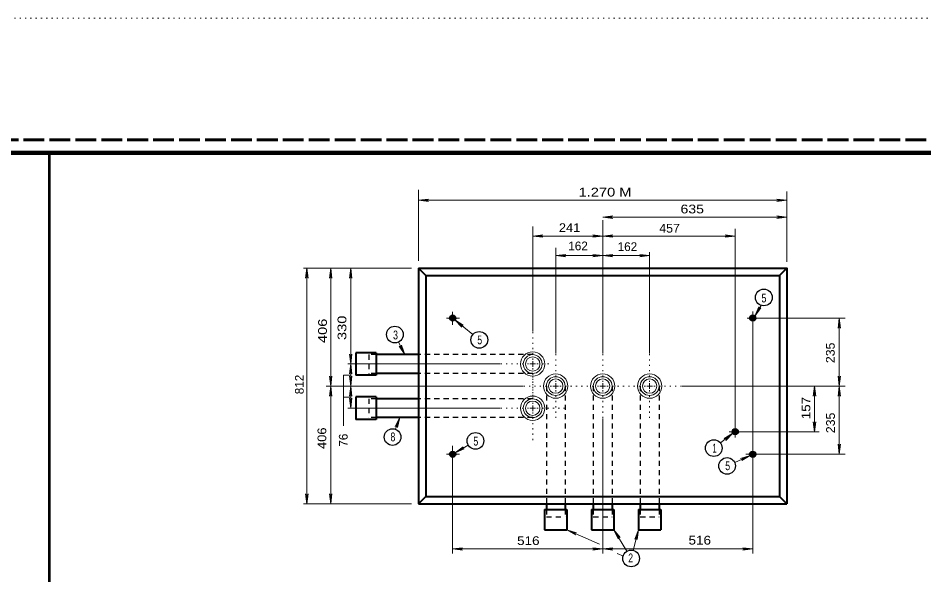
# Model space of a CAD drawing. Extents: x 312583 to 312854, y 144419 to 144597.
# Drawn here: x 312705.5 to 312784.1, y 144548.5 to 144596.8 of the extents above; entities that cross this region are included whole.
import ezdxf

# ---------------------------------------------------------------- set-up
doc = ezdxf.new("R2010")
doc.units = 0
doc.header["$LTSCALE"] = 0.3
for name, pattern in [('DOTTED', [1.5, 0.3, -1.2]), ('LONG_DASHED', [7.5, 6, -1.5]), ('SHORT_DASHED', [2.7, 1.5, -1.2])]:
    doc.linetypes.add(name, pattern=pattern)
for name, color, linetype, lineweight in [('1', 7, 'Continuous', 25), ('2', 7, 'Continuous', 13), ('52', 7, 'Continuous', 25), ('62', 7, 'DOTTED', 13), ('63', 7, 'LONG_DASHED', 60)]:
    doc.layers.add(name, color=color, linetype=linetype, lineweight=lineweight)

msp = doc.modelspace()

# ---------------------------------------------------------------- linework, layer by layer
at = {"layer": '1', "lineweight": 40}
for p, q in [((312740.216, 144575.0795), (312740.216, 144554.6325)), ((312740.86, 144574.4431), (312740.216, 144575.0795)), ((312771.5267, 144574.4431), (312772.163, 144575.0795)), ((312740.86, 144574.4431), (312740.86, 144555.2765)), ((312736.5437, 144567.7501), (312734.788, 144567.7501)), ((312734.788, 144567.7501), (312734.788, 144565.7951)), ((312736.5437, 144567.7501), (312736.5437, 144565.7951)), ((312740.216, 144567.5891), (312736.5437, 144567.5891)), ((312740.216, 144565.9561), (312736.5437, 144565.9561)), ((312736.5437, 144565.7951), (312734.788, 144565.7951)), ((312736.5437, 144563.9168), (312734.788, 144563.9168)), ((312734.788, 144563.9168), (312734.788, 144561.9618)), ((312736.5437, 144563.9168), (312736.5437, 144561.9618)), ((312740.216, 144563.7558), (312736.5437, 144563.7558)), ((312736.5437, 144561.9618), (312734.788, 144561.9618)), ((312740.216, 144562.1228), (312736.5437, 144562.1228)), ((312740.86, 144555.2765), (312740.216, 144554.6325)), ((312740.86, 144555.2765), (312771.5267, 144555.2765)), ((312771.5267, 144555.2765), (312772.163, 144554.6325)), ((312740.216, 144554.6325), (312772.163, 144554.6325)), ((312751.141, 144554.1571), (312751.141, 144552.4015)), ((312751.141, 144554.1571), (312753.0884, 144554.1571)), ((312751.302, 144554.6325), (312751.302, 144554.1571)), ((312752.935, 144554.6325), (312752.935, 144554.1571)), ((312753.0884, 144554.1571), (312753.0884, 144552.4015)), ((312755.212, 144554.1571), (312755.212, 144552.4015)), ((312755.212, 144554.1571), (312757.167, 144554.1571)), ((312755.373, 144554.6325), (312755.373, 144554.1571)), ((312757.006, 144554.6325), (312757.006, 144554.1571)), ((312757.167, 144554.1571), (312757.167, 144552.4015)), ((312759.2907, 144554.1571), (312759.2907, 144552.4015)), ((312759.2907, 144554.1571), (312761.238, 144554.1571)), ((312759.4517, 144554.6325), (312759.4517, 144554.1571)), ((312761.077, 144554.6325), (312761.077, 144554.1571)), ((312761.238, 144554.1571), (312761.238, 144552.4015)), ((312751.141, 144552.4015), (312753.0884, 144552.4015)), ((312755.212, 144552.4015), (312757.167, 144552.4015)), ((312759.2907, 144552.4015), (312761.238, 144552.4015))]:
    msp.add_line(p, q, dxfattribs=at)
at = {"layer": '1', "linetype": 'SHORT_DASHED'}
for p, q in [((312735.9074, 144567.5891), (312735.9074, 144565.9561)), ((312736.5437, 144567.5891), (312735.9074, 144567.5891)), ((312750.1214, 144567.5891), (312740.216, 144567.5891)), ((312736.5437, 144565.9561), (312735.9074, 144565.9561)), ((312750.1214, 144565.9561), (312740.216, 144565.9561)), ((312751.302, 144564.8598), (312751.302, 144554.6325)), ((312752.935, 144564.8598), (312752.935, 144554.6325)), ((312755.373, 144564.8598), (312755.373, 144554.6325)), ((312757.006, 144564.8598), (312757.006, 144554.6325)), ((312759.4517, 144564.8598), (312759.4517, 144554.6325)), ((312761.077, 144564.8598), (312761.077, 144554.6325)), ((312735.9074, 144563.7558), (312735.9074, 144562.1228)), ((312736.5437, 144563.7558), (312735.9074, 144563.7558)), ((312750.1214, 144563.7558), (312740.216, 144563.7558)), ((312736.5437, 144562.1228), (312735.9074, 144562.1228)), ((312750.1214, 144562.1228), (312740.216, 144562.1228)), ((312751.302, 144554.1571), (312751.302, 144553.5131)), ((312752.935, 144554.1571), (312752.935, 144553.5131)), ((312755.373, 144554.1571), (312755.373, 144553.5131)), ((312757.006, 144554.1571), (312757.006, 144553.5131)), ((312759.4517, 144554.1571), (312759.4517, 144553.5131)), ((312761.077, 144554.1571), (312761.077, 144553.5131)), ((312751.302, 144553.5131), (312752.935, 144553.5131)), ((312755.373, 144553.5131), (312757.006, 144553.5131)), ((312759.4517, 144553.5131), (312761.077, 144553.5131))]:
    msp.add_line(p, q, dxfattribs=at)
at = {"layer": '1', "lineweight": 158}
msp.add_lwpolyline([(312616.5, 144423.1446), (312616.5, 144585.0846), (312849, 144585.0846)], dxfattribs=at)
at = {"layer": '1', "lineweight": 40}
for points in [[(312740.216, 144575.0795), (312772.163, 144575.0795), (312772.163, 144554.6325)], [(312740.86, 144574.4431), (312771.5267, 144574.4431), (312771.5267, 144555.2765)]]:
    msp.add_lwpolyline(points, dxfattribs=at)
for centre, radius in [((312743.1722, 144570.7663), 0.2396), ((312743.1722, 144570.7663), 0.2156), ((312743.1722, 144570.7663), 0.1941), ((312743.1722, 144570.7663), 0.1747), ((312743.1722, 144570.7663), 0.1572), ((312743.1722, 144570.7663), 0.1415), ((312743.1722, 144570.7663), 0.1273), ((312743.1722, 144570.7663), 0.1146), ((312743.1722, 144570.7663), 0.1031), ((312743.1722, 144570.7663), 0.0928), ((312743.1722, 144570.7663), 0.0835), ((312743.1722, 144570.7663), 0.0752), ((312743.1722, 144570.7663), 0.0677), ((312743.1722, 144570.7663), 0.0609), ((312743.1722, 144570.7663), 0.0548), ((312769.2069, 144570.7663), 0.2396), ((312769.2069, 144570.7663), 0.2156), ((312769.2069, 144570.7663), 0.1941), ((312769.2069, 144570.7663), 0.1747), ((312769.2069, 144570.7663), 0.1572), ((312769.2069, 144570.7663), 0.1415), ((312769.2069, 144570.7663), 0.1273), ((312769.2069, 144570.7663), 0.1146), ((312769.2069, 144570.7663), 0.1031), ((312769.2069, 144570.7663), 0.0928), ((312769.2069, 144570.7663), 0.0835), ((312769.2069, 144570.7663), 0.0752), ((312769.2069, 144570.7663), 0.0677), ((312769.2069, 144570.7663), 0.0609), ((312769.2069, 144570.7663), 0.0548), ((312767.6895, 144560.9038), 0.2396), ((312767.6895, 144560.9038), 0.2156), ((312767.6895, 144560.9038), 0.1941), ((312767.6895, 144560.9038), 0.1747), ((312767.6895, 144560.9038), 0.1572), ((312767.6895, 144560.9038), 0.1415), ((312767.6895, 144560.9038), 0.1273), ((312767.6895, 144560.9038), 0.1146), ((312767.6895, 144560.9038), 0.1031), ((312767.6895, 144560.9038), 0.0928), ((312767.6895, 144560.9038), 0.0835), ((312767.6895, 144560.9038), 0.0752), ((312767.6895, 144560.9038), 0.0677), ((312767.6895, 144560.9038), 0.0609), ((312767.6895, 144560.9038), 0.0548), ((312743.1722, 144558.9469), 0.2396), ((312743.1722, 144558.9469), 0.2156), ((312743.1722, 144558.9469), 0.1941), ((312743.1722, 144558.9469), 0.1747), ((312743.1722, 144558.9469), 0.1572), ((312743.1722, 144558.9469), 0.1415), ((312743.1722, 144558.9469), 0.1273), ((312743.1722, 144558.9469), 0.1146), ((312743.1722, 144558.9469), 0.1031), ((312743.1722, 144558.9469), 0.0928), ((312743.1722, 144558.9469), 0.0835), ((312743.1722, 144558.9469), 0.0752), ((312743.1722, 144558.9469), 0.0677), ((312743.1722, 144558.9469), 0.0609), ((312743.1722, 144558.9469), 0.0548), ((312769.2069, 144558.9469), 0.2396), ((312769.2069, 144558.9469), 0.2156), ((312769.2069, 144558.9469), 0.1941), ((312769.2069, 144558.9469), 0.1747), ((312769.2069, 144558.9469), 0.1572), ((312769.2069, 144558.9469), 0.1415), ((312769.2069, 144558.9469), 0.1273), ((312769.2069, 144558.9469), 0.1146), ((312769.2069, 144558.9469), 0.1031), ((312769.2069, 144558.9469), 0.0928), ((312769.2069, 144558.9469), 0.0835), ((312769.2069, 144558.9469), 0.0752), ((312769.2069, 144558.9469), 0.0677), ((312769.2069, 144558.9469), 0.0609), ((312769.2069, 144558.9469), 0.0548)]:
    msp.add_circle(centre, radius, dxfattribs=at)
at = {"layer": '1', "lineweight": 13}
for centre, radius in [((312750.1201, 144566.7733), 1.0542), ((312750.1201, 144566.7733), 0.8146), ((312750.1201, 144566.7733), 0.6232), ((312752.1166, 144564.8566), 1.0542), ((312756.1895, 144564.8566), 1.0542), ((312760.2625, 144564.8566), 1.0542), ((312752.1166, 144564.8566), 0.8146), ((312752.1166, 144564.8566), 0.6232), ((312756.1895, 144564.8566), 0.8146), ((312756.1895, 144564.8566), 0.6232), ((312760.2625, 144564.8566), 0.8146), ((312760.2625, 144564.8566), 0.6232), ((312750.1201, 144562.9399), 1.0542), ((312750.1201, 144562.9399), 0.8146), ((312750.1201, 144562.9399), 0.6232)]:
    msp.add_circle(centre, radius, dxfattribs=at)
at = {"layer": '2', "lineweight": 53}
msp.add_line((312708.1809, 144585.0846), (312708.1809, 144423.0846), dxfattribs=at)
at = {"layer": '2'}
for p, q in [((312740.216, 144575.7388), (312740.216, 144581.8982)), ((312772.163, 144575.6315), (312772.163, 144581.7487)), ((312740.216, 144580.9791), (312741.0824, 144581.0864)), ((312740.216, 144580.9791), (312772.163, 144580.9791)), ((312740.216, 144580.9791), (312741.0824, 144580.8717)), ((312741.0824, 144581.0864), (312740.8064, 144580.9791)), ((312741.0824, 144580.8717), (312740.8064, 144580.9791)), ((312771.2967, 144581.0864), (312771.5727, 144580.9791)), ((312772.163, 144580.9791), (312771.2967, 144581.0864)), ((312771.2967, 144580.8717), (312771.5727, 144580.9791)), ((312772.163, 144580.9791), (312771.2967, 144580.8717)), ((312756.1934, 144579.5109), (312757.0597, 144579.6182)), ((312756.1934, 144579.5109), (312772.163, 144579.5109)), ((312756.1934, 144579.5109), (312757.0597, 144579.4036)), ((312756.1934, 144567.6811), (312756.1934, 144579.2578)), ((312757.0597, 144579.6182), (312756.7837, 144579.5109)), ((312757.0597, 144579.4036), (312756.7837, 144579.5109)), ((312771.2967, 144579.6182), (312771.5727, 144579.5109)), ((312772.163, 144579.5109), (312771.2967, 144579.6182)), ((312771.2967, 144579.4036), (312771.5727, 144579.5109)), ((312772.163, 144579.5109), (312771.2967, 144579.4036)), ((312750.1214, 144569.5978), (312750.1214, 144578.7058)), ((312767.6934, 144578.4911), (312767.6934, 144560.4055)), ((312750.1214, 144577.8787), (312750.9877, 144577.9861)), ((312750.1214, 144577.8787), (312756.1934, 144577.8787)), ((312750.1214, 144577.8787), (312750.9877, 144577.7714)), ((312750.9877, 144577.9861), (312750.7117, 144577.8787)), ((312750.9877, 144577.7714), (312750.7117, 144577.8787)), ((312755.327, 144577.9861), (312755.603, 144577.8787)), ((312756.1934, 144577.8787), (312755.327, 144577.9861)), ((312755.327, 144577.7714), (312755.603, 144577.8787)), ((312756.1934, 144577.8787), (312755.327, 144577.7714)), ((312756.1934, 144577.8787), (312757.0597, 144577.9861)), ((312756.1934, 144577.8787), (312767.6934, 144577.8787)), ((312756.1934, 144577.8787), (312757.0597, 144577.7714)), ((312757.0597, 144577.9861), (312756.7837, 144577.8787)), ((312757.0597, 144577.7714), (312756.7837, 144577.8787)), ((312766.827, 144577.9861), (312767.103, 144577.8787)), ((312767.6934, 144577.8787), (312766.827, 144577.9861)), ((312766.827, 144577.7714), (312767.103, 144577.8787)), ((312767.6934, 144577.8787), (312766.827, 144577.7714)), ((312752.1147, 144567.6811), (312752.1147, 144576.8658)), ((312752.1147, 144576.1758), (312752.981, 144576.2831)), ((312752.1147, 144576.1758), (312752.981, 144576.0685)), ((312752.1147, 144576.1758), (312756.1934, 144576.1758)), ((312752.981, 144576.2831), (312752.705, 144576.1758)), ((312752.981, 144576.0685), (312752.705, 144576.1758)), ((312755.327, 144576.2831), (312755.603, 144576.1758)), ((312756.1934, 144576.1758), (312755.327, 144576.2831)), ((312755.327, 144576.0685), (312755.603, 144576.1758)), ((312756.1934, 144576.1758), (312755.327, 144576.0685)), ((312756.1934, 144576.1758), (312757.0597, 144576.2831)), ((312756.1934, 144576.1758), (312760.2644, 144576.1758)), ((312756.1934, 144576.1758), (312757.0597, 144576.0685)), ((312757.0597, 144576.2831), (312756.7837, 144576.1758)), ((312757.0597, 144576.0685), (312756.7837, 144576.1758)), ((312759.398, 144576.2831), (312759.674, 144576.1758)), ((312760.2644, 144576.1758), (312759.398, 144576.2831)), ((312759.398, 144576.0685), (312759.674, 144576.1758)), ((312760.2644, 144576.1758), (312759.398, 144576.0685)), ((312760.2644, 144567.6811), (312760.2644, 144576.4825)), ((312739.618, 144575.0795), (312730.234, 144575.0795)), ((312730.5254, 144575.0795), (312730.418, 144574.2131)), ((312730.5254, 144554.6325), (312730.5254, 144575.0795)), ((312730.5254, 144575.0795), (312730.6327, 144574.2131)), ((312732.5954, 144575.0795), (312732.488, 144574.2131)), ((312732.5954, 144575.0795), (312732.7027, 144574.2131)), ((312734.3357, 144575.0795), (312734.2284, 144574.2131)), ((312734.3357, 144575.0795), (312734.443, 144574.2131)), ((312730.418, 144574.2131), (312730.5254, 144574.4891)), ((312730.6327, 144574.2131), (312730.5254, 144574.4891)), ((312732.488, 144574.2131), (312732.5954, 144574.4891)), ((312732.7027, 144574.2131), (312732.5954, 144574.4891)), ((312734.2284, 144574.2131), (312734.3357, 144574.4891)), ((312734.443, 144574.2131), (312734.3357, 144574.4891)), ((312769.9244, 144571.8595), (312769.3877, 144570.9395)), ((312769.3877, 144570.9395), (312769.7327, 144571.7445)), ((312769.3877, 144570.9395), (312769.9167, 144571.6371)), ((312769.7327, 144571.7445), (312769.6867, 144571.4531)), ((312769.9167, 144571.6371), (312769.6867, 144571.4531)), ((312742.6387, 144570.7631), (312743.758, 144570.7631)), ((312743.1754, 144571.2998), (312743.1754, 144570.1805)), ((312744.9234, 144569.3295), (312743.3594, 144570.6175)), ((312743.3594, 144570.6175), (312743.9574, 144569.9811)), ((312743.3594, 144570.6175), (312744.0954, 144570.1498)), ((312768.736, 144570.7631), (312777.2154, 144570.7631)), ((312769.2037, 144571.3228), (312769.2037, 144550.3315)), ((312776.717, 144570.7631), (312776.6097, 144569.8968)), ((312776.717, 144570.7631), (312776.8244, 144569.8968)), ((312743.9574, 144569.9811), (312743.8117, 144570.2418)), ((312744.0954, 144570.1498), (312743.8117, 144570.2418)), ((312776.6097, 144569.8968), (312776.717, 144570.1728)), ((312776.8244, 144569.8968), (312776.717, 144570.1728)), ((312738.491, 144568.6778), (312739.0277, 144567.5891)), ((312738.5447, 144568.3175), (312738.767, 144568.1181)), ((312739.0277, 144567.5891), (312738.5447, 144568.3175)), ((312738.7364, 144568.4095), (312738.767, 144568.1181)), ((312739.0277, 144567.5891), (312738.7364, 144568.4095)), ((312734.2284, 144567.6428), (312734.3357, 144567.3668)), ((312734.3357, 144566.7765), (312734.2284, 144567.6428)), ((312734.443, 144567.6428), (312734.3357, 144567.3668)), ((312734.3357, 144566.7765), (312734.443, 144567.6428)), ((312747.3, 144566.7765), (312734.0904, 144566.7765)), ((312734.3357, 144566.7765), (312734.2284, 144565.9101)), ((312734.3357, 144566.7765), (312734.443, 144565.9101)), ((312750.1214, 144566.7765), (312749.876, 144566.7765)), ((312750.1214, 144566.7765), (312750.1214, 144567.0218)), ((312750.1214, 144566.7765), (312750.3667, 144566.7765)), ((312750.1214, 144566.7765), (312750.1214, 144566.5311)), ((312734.2284, 144565.9101), (312734.3357, 144566.1861)), ((312734.443, 144565.9101), (312734.3357, 144566.1861)), ((312732.488, 144565.7261), (312732.5954, 144565.4501)), ((312732.5954, 144564.8598), (312732.488, 144565.7261)), ((312732.7027, 144565.7261), (312732.5954, 144565.4501)), ((312732.5954, 144564.8598), (312732.7027, 144565.7261)), ((312734.2284, 144565.7261), (312734.3357, 144565.4501)), ((312734.3357, 144564.8598), (312734.2284, 144565.7261)), ((312734.443, 144565.7261), (312734.3357, 144565.4501)), ((312734.3357, 144564.8598), (312734.443, 144565.7261)), ((312752.1147, 144564.8598), (312752.1147, 144565.1051)), ((312756.1934, 144564.8598), (312756.1934, 144565.1051)), ((312760.2644, 144564.8598), (312760.2644, 144565.1051)), ((312776.6097, 144565.7261), (312776.717, 144565.4501)), ((312776.717, 144564.8598), (312776.6097, 144565.7261)), ((312776.8244, 144565.7261), (312776.717, 144565.4501)), ((312776.717, 144564.8598), (312776.8244, 144565.7261)), ((312749.2934, 144564.8598), (312732.2044, 144564.8598)), ((312732.5954, 144564.8598), (312732.488, 144563.9935)), ((312732.5954, 144564.8598), (312732.7027, 144563.9935)), ((312734.3357, 144564.8598), (312734.2284, 144563.9935)), ((312734.3357, 144564.8598), (312734.443, 144563.9935)), ((312752.1147, 144564.8598), (312751.8694, 144564.8598)), ((312752.1147, 144564.8598), (312752.36, 144564.8598)), ((312752.1147, 144564.8598), (312752.1147, 144564.6145)), ((312756.1934, 144564.8598), (312755.948, 144564.8598)), ((312756.1934, 144564.8598), (312756.4387, 144564.8598)), ((312756.1934, 144564.8598), (312756.1934, 144564.6145)), ((312760.2644, 144564.8598), (312760.019, 144564.8598)), ((312760.2644, 144564.8598), (312760.5097, 144564.8598)), ((312760.2644, 144564.8598), (312760.2644, 144564.6145)), ((312763.0857, 144564.8598), (312777.2154, 144564.8598)), ((312774.5627, 144564.8598), (312774.4554, 144563.9935)), ((312774.5627, 144560.9038), (312774.5627, 144564.8598)), ((312774.5627, 144564.8598), (312774.67, 144563.9935)), ((312776.717, 144564.8598), (312776.6097, 144563.9935)), ((312776.717, 144564.8598), (312776.8244, 144563.9935)), ((312732.488, 144563.9935), (312732.5954, 144564.2695)), ((312732.7027, 144563.9935), (312732.5954, 144564.2695)), ((312734.2284, 144563.9935), (312734.3357, 144564.2695)), ((312734.2284, 144563.8095), (312734.3357, 144563.5335)), ((312734.3357, 144562.9431), (312734.2284, 144563.8095)), ((312734.443, 144563.9935), (312734.3357, 144564.2695)), ((312734.443, 144563.8095), (312734.3357, 144563.5335)), ((312734.3357, 144562.9431), (312734.443, 144563.8095)), ((312774.4554, 144563.9935), (312774.5627, 144564.2695)), ((312774.67, 144563.9935), (312774.5627, 144564.2695)), ((312776.6097, 144563.9935), (312776.717, 144564.2695)), ((312776.8244, 144563.9935), (312776.717, 144564.2695)), ((312747.3, 144562.9431), (312734.0904, 144562.9431)), ((312750.1214, 144562.9431), (312749.876, 144562.9431)), ((312750.1214, 144562.9431), (312750.1214, 144563.1885)), ((312750.1214, 144562.9431), (312750.3667, 144562.9431)), ((312750.1214, 144562.9431), (312750.1214, 144562.6978)), ((312738.606, 144562.1228), (312738.1997, 144561.3561)), ((312738.2227, 144561.1185), (312738.606, 144562.1228)), ((312738.606, 144562.1228), (312738.399, 144561.2795)), ((312756.1934, 144562.0385), (312756.1934, 144550.3315)), ((312738.1997, 144561.3561), (312738.399, 144561.5708)), ((312738.399, 144561.2795), (312738.399, 144561.5708)), ((312774.4554, 144561.7701), (312774.5627, 144561.4941)), ((312774.5627, 144560.9038), (312774.4554, 144561.7701)), ((312774.67, 144561.7701), (312774.5627, 144561.4941)), ((312774.5627, 144560.9038), (312774.67, 144561.7701)), ((312766.3977, 144559.9301), (312767.4864, 144560.7735)), ((312767.4864, 144560.7735), (312766.735, 144560.3211)), ((312766.735, 144560.3211), (312767.0187, 144560.4055)), ((312767.4864, 144560.7735), (312766.8654, 144560.1525)), ((312766.8654, 144560.1525), (312767.0187, 144560.4055)), ((312767.172, 144560.9038), (312774.9614, 144560.9038)), ((312743.1754, 144559.6695), (312743.1754, 144550.3315)), ((312744.5247, 144559.7385), (312743.3824, 144559.0638)), ((312743.3824, 144559.0638), (312744.0724, 144559.6005)), ((312744.0724, 144559.6005), (312743.8884, 144559.3628)), ((312776.6097, 144559.8151), (312776.717, 144559.5391)), ((312776.717, 144558.9488), (312776.6097, 144559.8151)), ((312776.8244, 144559.8151), (312776.717, 144559.5391)), ((312776.717, 144558.9488), (312776.8244, 144559.8151)), ((312742.6387, 144558.9488), (312743.758, 144558.9488)), ((312743.3824, 144559.0638), (312744.1797, 144559.4088)), ((312744.1797, 144559.4088), (312743.8884, 144559.3628)), ((312767.6397, 144558.2281), (312768.989, 144558.8491)), ((312768.989, 144558.8491), (312768.1534, 144558.5885)), ((312768.989, 144558.8491), (312768.2454, 144558.3891)), ((312768.6057, 144558.9488), (312777.2154, 144558.9488)), ((312768.1534, 144558.5885), (312768.4524, 144558.6038)), ((312768.2454, 144558.3891), (312768.4524, 144558.6038)), ((312730.418, 144555.4988), (312730.5254, 144555.2228)), ((312730.5254, 144554.6325), (312730.418, 144555.4988)), ((312730.6327, 144555.4988), (312730.5254, 144555.2228)), ((312730.5254, 144554.6325), (312730.6327, 144555.4988)), ((312732.488, 144555.4988), (312732.5954, 144555.2228)), ((312732.5954, 144554.6325), (312732.488, 144555.4988)), ((312732.7027, 144555.4988), (312732.5954, 144555.2228)), ((312732.5954, 144554.6325), (312732.7027, 144555.4988)), ((312739.618, 144554.6325), (312730.234, 144554.6325)), ((312753.0884, 144552.4015), (312753.8397, 144551.9491)), ((312753.0884, 144552.4015), (312753.924, 144552.1408)), ((312755.9174, 144551.1365), (312753.0884, 144552.4015)), ((312753.8397, 144551.9491), (312753.6327, 144552.1561)), ((312753.924, 144552.1408), (312753.6327, 144552.1561)), ((312758.2864, 144550.5308), (312757.167, 144552.4015)), ((312757.167, 144552.4015), (312757.5197, 144551.5965)), ((312757.167, 144552.4015), (312757.7037, 144551.7115)), ((312757.5197, 144551.5965), (312757.466, 144551.8878)), ((312757.7037, 144551.7115), (312757.466, 144551.8878)), ((312758.8384, 144550.6075), (312759.2907, 144552.4015)), ((312759.2907, 144552.4015), (312758.9687, 144551.5811)), ((312758.9687, 144551.5811), (312759.145, 144551.8265)), ((312759.1834, 144551.5351), (312759.145, 144551.8265)), ((312759.2907, 144552.4015), (312759.1834, 144551.5351)), ((312743.1754, 144550.7301), (312744.0417, 144550.8375)), ((312743.1754, 144550.7301), (312744.0417, 144550.6228)), ((312744.0417, 144550.8375), (312743.7657, 144550.7301)), ((312744.0417, 144550.6228), (312743.7657, 144550.7301)), ((312755.327, 144550.8375), (312755.603, 144550.7301)), ((312756.1934, 144550.7301), (312755.327, 144550.8375)), ((312755.327, 144550.6228), (312755.603, 144550.7301)), ((312756.1934, 144550.7301), (312755.327, 144550.6228)), ((312756.1934, 144550.7301), (312757.0597, 144550.8375)), ((312756.1934, 144550.7301), (312757.0597, 144550.6228)), ((312757.0597, 144550.8375), (312756.7837, 144550.7301)), ((312757.0597, 144550.6228), (312756.7837, 144550.7301)), ((312757.995, 144550.0891), (312757.4584, 144550.3345)), ((312768.3374, 144550.8375), (312768.6134, 144550.7301)), ((312769.2037, 144550.7301), (312768.3374, 144550.8375)), ((312768.3374, 144550.6228), (312768.6134, 144550.7301)), ((312769.2037, 144550.7301), (312768.3374, 144550.6228))]:
    msp.add_line(p, q, dxfattribs=at)
at = {"layer": '2', "linetype": 'DOTTED'}
for p, q in [((312750.1214, 144567.1445), (312750.1214, 144569.5978)), ((312752.1147, 144565.2278), (312752.1147, 144567.6811)), ((312756.1934, 144565.2278), (312756.1934, 144567.6811)), ((312760.2644, 144565.2278), (312760.2644, 144567.6811)), ((312749.7534, 144566.7765), (312747.3, 144566.7765)), ((312750.4894, 144566.7765), (312751.785, 144566.7765)), ((312750.1214, 144566.4085), (312750.1214, 144563.9551)), ((312750.1214, 144563.3111), (312750.1214, 144565.7645)), ((312751.7467, 144564.8598), (312749.2934, 144564.8598)), ((312752.1147, 144564.4918), (312752.1147, 144562.0385)), ((312752.4827, 144564.8598), (312754.3687, 144564.8598)), ((312755.8254, 144564.8598), (312754.3687, 144564.8598)), ((312756.1934, 144564.4918), (312756.1934, 144562.0385)), ((312756.5614, 144564.8598), (312758.2787, 144564.8598)), ((312759.8964, 144564.8598), (312758.2787, 144564.8598)), ((312760.2644, 144564.4918), (312760.2644, 144562.0385)), ((312760.6324, 144564.8598), (312763.0857, 144564.8598)), ((312749.7534, 144562.9431), (312747.3, 144562.9431)), ((312750.4894, 144562.9431), (312752.9427, 144562.9431)), ((312750.1214, 144562.5751), (312750.1214, 144560.1218))]:
    msp.add_line(p, q, dxfattribs=at)
at = {"layer": '2'}
for points in [[(312732.5954, 144554.6325), (312732.5954, 144564.8598), (312732.5954, 144575.0795)], [(312734.3357, 144562.9431), (312734.3357, 144564.8598), (312734.3357, 144566.7765), (312734.3357, 144575.0795)], [(312776.717, 144558.9488), (312776.717, 144564.8598), (312776.717, 144570.7631)], [(312743.1754, 144550.7301), (312756.1934, 144550.7301), (312769.2037, 144550.7301)]]:
    msp.add_lwpolyline(points, dxfattribs=at)
at = {"layer": '2', "lineweight": 25}
for centre in [(312770.1671, 144572.5482), (312738.1658, 144569.3275), (312745.4869, 144568.8663), (312737.9652, 144560.4368), (312745.1515, 144560.102), (312765.8272, 144559.4816), (312766.9791, 144557.9298), (312758.6563, 144549.9072)]:
    msp.add_circle(centre, 0.7254, dxfattribs=at)
at = {"layer": '52', "lineweight": 13}
for p, q in [((312733.707, 144561.4098), (312733.707, 144565.8105)), ((312733.707, 144565.8105), (312734.3357, 144565.8105)), ((312733.707, 144564.8598), (312734.3357, 144564.8598)), ((312733.707, 144563.8938), (312734.3434, 144563.8938))]:
    msp.add_line(p, q, dxfattribs=at)
at = {"layer": '62'}
msp.add_line((312601.2, 144596.7846), (312853.5, 144596.7846), dxfattribs=at)
at = {"layer": '63'}
msp.add_line((312851.75, 144586.2246), (312583.526, 144586.2246), dxfattribs=at)

# ---------------------------------------------------------------- texts
at = {"layer": '2'}
for s, width, p in [('1.270 M', 1.25, (312754.0967, 144581.3065)), ('635 ', 1.2, (312762.9386, 144579.8422)), ('241 ', 1.1, (312752.3861, 144578.223)), ('457', 1.05, (312761.1004, 144578.1738)), ('5', 0.75, (312769.9643, 144572.1184)), ('3', 0.75, (312738.0076, 144568.9111)), ('5', 0.75, (312745.3112, 144568.4869)), ('8', 0.75, (312737.7826, 144560.0715)), ('5', 0.75, (312744.9739, 144559.6983)), ('1', 0.5, (312765.7112, 144559.0952)), ('5', 0.75, (312766.8189, 144557.5646)), ('516 ', 1.15, (312748.7645, 144551.0696)), ('516 ', 1.15, (312763.6357, 144551.1099)), ('2', 0.75, (312758.403, 144549.5722))]:
    msp.add_text(s, height=0.76, dxfattribs=dict(at, width=width)).set_placement(p)
for p in [(312753.2038, 144576.6376), (312757.4864, 144576.5754)]:
    msp.add_text('162', height=0.76, dxfattribs=at).set_placement(p)
for s, width, p in [('406 ', 1.25, (312732.267, 144568.5895)), ('330 ', 1.25, (312733.9532, 144568.8541)), ('235', 1.05, (312776.3169, 144566.8512)), ('157 ', 1.15, (312774.2014, 144561.9762)), ('235', 1.05, (312776.3331, 144560.775)), ('406', 1.1, (312732.2129, 144559.401))]:
    msp.add_text(s, height=0.76, rotation=90, dxfattribs=dict(at, width=width)).set_placement(p)
for s, p in [('812', (312730.2564, 144564.1499)), ('76', (312734.0674, 144559.5996))]:
    msp.add_text(s, height=0.76, rotation=90, dxfattribs=at).set_placement(p)

doc.saveas('drawing.dxf')
